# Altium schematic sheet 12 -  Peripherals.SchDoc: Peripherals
size A3; Date: 01-DEC-2018; CompanyName: Octavo Systems LLC; Address2: Austin,TX; Address3: USA; DocumentNumber: DK2 RefDes; Revision: C-01; SheetNumber: 12; SheetTotal: 14
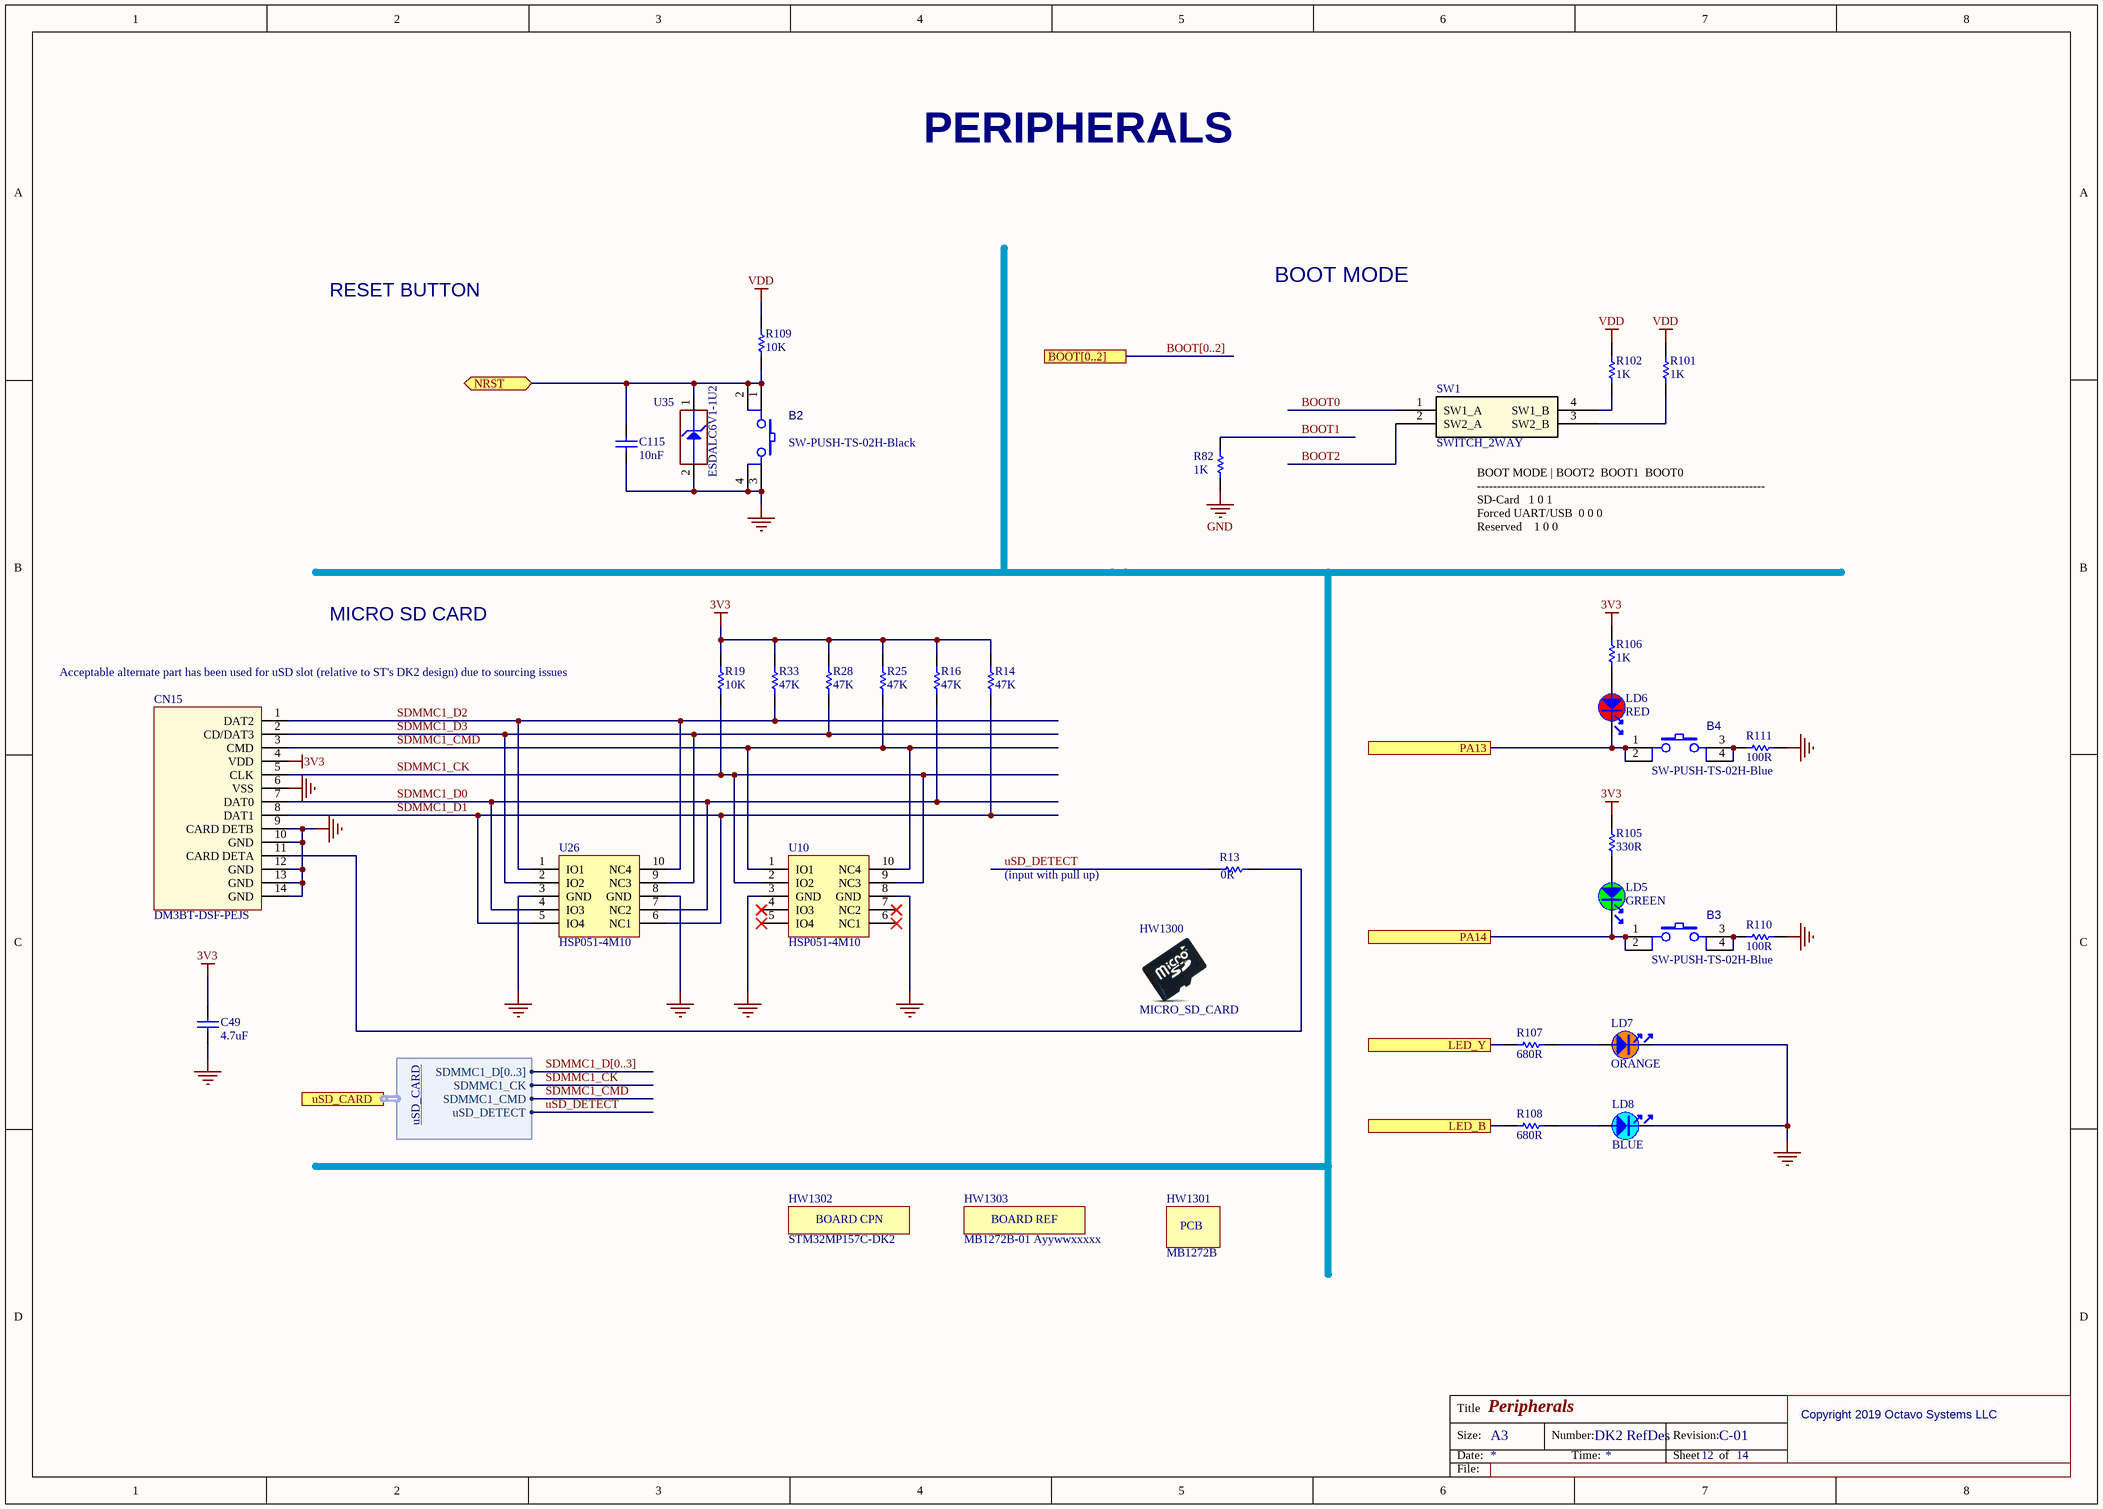
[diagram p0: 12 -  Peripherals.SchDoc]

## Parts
B2  value SW-PUSH-TS-02H-Black  [SWI_JIUBABA_C-TS-02H-2-5-K-V-T_R_BLACK]
B3  SW-PUSH-TS-02H-Blue  [SWI_JIUBABA_C-TS-02H-2-5-B-V-T_R_BLUE]
B4  SW-PUSH-TS-02H-Blue  [SWI_JIUBABA_C-TS-02H-2-5-B-V-T_R_BLUE]
C49  value 4.7uF  [C0402]
C115  value 10nF  [C0402]  (hidden comment: Capacitor)
CN15  DM3BT-DSF-PEJS  [DM3BT-DSF-PEJS]
HW1300  Micro_SD_card  (mechanical)
HW1301  value MB1272B  (hidden comment: PCB)  (mechanical)
HW1302  value STM32MP157C-DK2  [STICKER_BOARD-CPN_25X5]  (hidden comment: ​PCH W35 footprint requested to have a space on board for stickers.)  (mechanical)
HW1303  value MB1272B-01 Ayywwxxxxx  [STICKER_BOARD-REF_25X5]  (hidden comment: STICKER_BOARD_REF)  (mechanical)
LD5  value GREEN  [LED_0603_GREEN]
LD6  value RED  [LED_0603_RED]
LD7  value ORANGE  [LED_0603_ORANGE_H0P4]  (hidden comment: LED_orange)
LD8  value BLUE  [LED_0603_SMD-B_BLUE_H0P4]  (hidden comment: ​reference from jiubaba)
R13  value 0R  [R0402]
R14  value 47K  [R0402]
R16  value 47K  [R0402]
R19  value 10K  [R0402]
R25  value 47K  [R0402]
R28  value 47K  [R0402]
R33  value 47K  [R0402]
R82  value 1K  [R0402]  (hidden comment: Resistor)
R101  value 1K  [R0402]
R102  value 1K  [R0402]
R105  value 330R  [R0402]
R106  value 1K  [R0402]
R107  value 680R  [R0402]  (hidden comment: Resistor)
R108  value 680R  [R0402]  (hidden comment: Resistor)
R109  value 10K  [R0402]
R110  value 100R  [R0402]
R111  value 100R  [R0402]
SW1  SWITCH_2WAY  [SWI_C&K_SDA02H1SBD_2POS]
U10  HSP051-4M10  [ESD_UQFN-10L_2P5X1_P050]
U26  HSP051-4M10  [ESD_UQFN-10L_2P5X1_P050]
U35  value ESDALC6V1-1U2  [ESD_ST0201]  (hidden comment: ESD-TRANSIL)

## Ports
BOOT[0..2], LED_B, LED_Y, NRST (bidir), PA13, PA14, uSD_CARD (harness uSD_CARD)

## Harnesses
uSD_CARD: SDMMC1_D[0..3], SDMMC1_CK, SDMMC1_CMD, uSD_DETECT

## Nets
3V3: C49.1 CN15.4(VDD) R14.2 R16.2 R19.2 R25.2 R28.2 R33.2 R105.2 R106.2
GND: B2.3 B2.4 C49.2 C115.1 CN15.6(VSS) CN15.9(CARD_DETB) CN15.10(GND) CN15.12(GND) CN15.13(GND) CN15.14(GND) LD7.2 LD8.2 R82.1 R110.2 R111.2 U10.3(GND) U10.8(GND) U26.3(GND) U26.8(GND) U35.2(GND)
VDD: R101.2 R102.2 R109.2
BOOT0: SW1.1(SW1_A)
BOOT1: R82.2
BOOT2: SW1.2(SW2_A)
LED_B: R108.1 ; port LED_B
LED_Y: R107.1 ; port LED_Y
NRST: B2.1 B2.2 C115.2 R109.1 U35.1(IO1) ; port NRST
PA13: B4.1 B4.2 LD6.2 ; port PA13
PA14: B3.1 B3.2 LD5.2 ; port PA14
SDMMC1_CK: CN15.5(CLK) R19.1 U10.2(IO2) U10.9(NC3) ; port uSD_CARD.SDMMC1_CK
SDMMC1_CMD: CN15.3(CMD) R25.1 U10.1(IO1) U10.10(NC4) ; port uSD_CARD.SDMMC1_CMD
SDMMC1_D0: CN15.7(DAT0) R16.1 U26.4(IO3) U26.7(NC2)
SDMMC1_D1: CN15.8(DAT1) R14.1 U26.5(IO4) U26.6(NC1)
SDMMC1_D2: CN15.1(DAT2) R33.1 U26.1(IO1) U26.10(NC4)
SDMMC1_D3: CN15.2(CD/DAT3) R28.1 U26.2(IO2) U26.9(NC3)
uSD_DETECT: R13.1 ; port uSD_CARD.uSD_DETECT
NetB3_3: B3.3 B3.4 R110.1
NetB4_3: B4.3 B4.4 R111.1
NetCN15_11: CN15.11(CARD_DETA) R13.2
NetLD5_1: LD5.1 R105.1
NetLD6_1: LD6.1 R106.1
NetLD7_1: LD7.1 R107.2
NetLD8_1: LD8.1 R108.2
NetR101_1: R101.1 SW1.3(SW2_B)
NetR102_1: R102.1 SW1.4(SW1_B)

Not connected (* = marked no-connect by the designer): U10 4(IO3)* 5(IO4)* 6(NC1)* 7(NC2)*

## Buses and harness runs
bus BOOT[0..2] = port BOOT[0..2]
bus SDMMC1_D[0..3]

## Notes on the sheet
- PERIPHERALS
- RESET BUTTON
- BOOT MODE
- (near SW1) BOOT MODE	|	BOOT2 	BOOT1 	BOOT0
  ------------------------------------------------------------------------
  SD-Card			1	0	1
  Forced UART/USB		0	0	0
  Reserved 			1	0	0
- MICRO SD CARD
- (near R19) Acceptable alternate part has been used for uSD slot (relative to ST's DK2 design) due to sourcing issues
- (input with pull up)
- Copyright 2019 Octavo Systems LLC

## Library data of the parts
B2 = MCD-00171: Switch HW SMD black; Manufacturer_Part_Number: C-TS-02H-2.5-K-V-T/R BLACK; Manufacturer: JIUBABA; Part_Type: Misc; Provided_By: Subcon; Initial_Board_Reference: MB1264
B3 B4 = MCD-00172: Switch HW SMD blue; Part_Type: Misc; Manufacturer_Part_Number: C-TS-02H-2.5-B-V-T/R BLUE; Manufacturer: JIUBABA; Provided_By: Subcon; Initial_Board_Reference: MB1264
C49 = MCD-01356: Capacitor, MLCC, 4.7uF, 6V3, X5R, 20%, 0402, T=0,5mm; Manufacturer_Part_Number: GRM155R60J475ME47; Manufacturer: MURATA; Provided_By: SUBCO; Initial_Board_Reference: MB1372; Item Type: Item; Path: ws/MCD_ApplicationBoards/Lists/MCDPARTSdatabase
C115 = MCD-00011: Capacitor, MLCC, 10nF, 16V, X7R, 10%, 0402, T=0.5mm; Manufacturer_Part_Number: CC0402KRX7R7BB103; Manufacturer: YAGEO; Provided_By: Subcon; Initial_Board_Reference: MB1274
CN15 = DM3BT-DSF-PEJS: Micro SD SMT bottom conn push-push; Manufacturer: Hirose
HW1300 = MCD-01200: MICRO_SD_CARD Standard min 4GB; Part_Type: Misc; Provided_By: Subcon; Initial_Board_Reference: MB1372
HW1301 = MCD-00216: PCB, xxxx for PCB ref, Y for revision; Part_Type: Mechanical; Provided_By: Subcon; Initial_Board_Reference: MB1319
HW1302 = MCD-00547: Sticker to mention board CPN code; Part_Type: Mechanical; Manufacturer_Part_Number: NA; Provided_By: Subcon; Initial_Board_Reference: MB1319
HW1303 = MCD-00235: Sticker to mention board reference + serial number; Part_Type: Mechanical; Manufacturer_Part_Number: NA; Provided_By: Subcon; Initial_Board_Reference: MB1319
LD5 = MCD-00050: LED, Green, 0603; Manufacturer_Part_Number: 19-213SYGC/S530-E2/TR8; Manufacturer: EVERLIGHT; Part_Type: Display; ECCN_US: EAR99; ECCN_EU: NEC; Provided_By: Subcon; Initial_Board_Reference: mb1274
LD6 = MCD-00049: LED, Red, 0603; Manufacturer_Part_Number: 19-213-R6C-AP1Q2B/3T; Manufacturer: EVERLIGHT; Part_Type: Display; ECCN_US: EAR99; ECCN_EU: NEC; Provided_By: Subcon; Initial_Board_Reference: mb1274
LD7 = MCD-00321: LED, Orange, 0603; Part_Type: Display; Manufacturer_Part_Number: 19-217/S2C-AM2N2VY/3T; Manufacturer: EVERLIGHT; ECCN_US: EAR99; ECCN_EU: NEC; Provided_By: Subcon; Initial_Board_Reference: MB1311
LD8 = MCD-01131: LED Blue, 0603 SMD, Forward Voltage Min=2,8V, Max=3,1V; Part_Type: Display; Manufacturer_Part_Number: 19-217-BHC-ZL1M2RY-3T; Manufacturer: EVERLIGHT; Provided_By: Subcon; Initial_Board_Reference: MB1272
R13 = MCD-00052: Resistor,0R,0402,5%,1/16W; Manufacturer_Part_Number: RC0402JR-070RL; Manufacturer: YAGEO; Provided_By: Subcon; Initial_Board_Reference: mb1274
R14 R16 R25 R28 R33 = MCD-00063: Resistor,47K,0402,1%,1/16W; Manufacturer_Part_Number: RC0402FR-0747KL; Manufacturer: YAGEO; Provided_By: Subcon; Initial_Board_Reference: mb1274
R19 R109 = MCD-00053: Resistor,10K,0402,1%,1/16W; Manufacturer_Part_Number: RC0402FR-0710KL; Manufacturer: YAGEO; Provided_By: subcon; Initial_Board_Reference: mb1274
R82 = MCD-00061: Resistor,1K,0402,1%,1/16W; Manufacturer_Part_Number: RC0402FR-071KL; Manufacturer: YAGEO; Provided_By: Subcon; Initial_Board_Reference: MB1274
R101 R102 R106 = MCD-00061: Resistor,1K,0402,1%,1/16W; Manufacturer_Part_Number: RC0402FR-071KL; Manufacturer: YAGEO; Provided_By: Subcon; Initial_Board_Reference: mb1274
R105 = MCD-00062: Resistor,330R,0402,1%,1/16W; Manufacturer_Part_Number: RC0402FR-07330RL; Manufacturer: YAGEO; Provided_By: Subcon; Initial_Board_Reference: mb1274
R107 R108 = MCD-00507: Resistor,680R,0402,1%,1/16W; Manufacturer_Part_Number: RC0402FR-07680RL; Manufacturer: YAGEO; Provided_By: Subcon
R110 R111 = MCD-00067: Resistor,100R,0402,1%,1/16W; Manufacturer_Part_Number: RC0402FR-07100RL; Manufacturer: YAGEO; Provided_By: Subcon; Initial_Board_Reference: mb1274
SW1 = MCD-00658: Dip Switch ,2Position ,Surface Mount Slide (Standard) ,2.54 pitch,25mA 24VDC; Part_Type: Misc; Manufacturer_Part_Number: SDA02H1SBD; Manufacturer: C&K; Provided_By: Subcon; Initial_Board_Reference: MB1272
U10 U26 = MCD-00667: 4-line ESD protection for high speed lines; Part_Type: Diode; Manufacturer: STMICROELECTRONICS; ECCN_US: EAR99; ECCN_EU: NEC; Provided_By: Subcon; Initial_Board_Reference: MB1331
U35 = MCD-00170: ESD protection 6V1; Part_Type: Diode; Manufacturer: STMICROELECTRONICS; ECCN_US: EAR99; ECCN_EU: NEC; Provided_By: Subcon; Initial_Board_Reference: MB1274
